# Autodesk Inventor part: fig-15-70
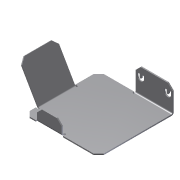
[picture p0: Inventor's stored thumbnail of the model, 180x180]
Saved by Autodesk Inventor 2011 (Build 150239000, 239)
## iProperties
Shininess: 77.0
Angle Display Precision: 2
Document Length Units: 11269
Document Angle Units: 11279
Document Time Units: 11290
Document Mass Units: 11283
Document Length Units Precision: 3
Document Angle Units Precision: 2
Created: 2002-04
Part Number: fig-15-70
Document SubType Name: Sheet Metal
Density: 1 g/cm^3
Sheet Metal Rule: Default
Density: 0.0
Volumn: 0.0
Area: 0.0
PropertySet Name: Model Information
Control State: 0
Master: False
Checked Out: False
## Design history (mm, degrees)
node "Face1"
  sketch "Sketch1"
    geometry: L1 (12.647, 25.882)-(12.647, -14.118); L2 (12.647, -14.118)-(-17.353, -14.118); L3 (-17.353, -14.118)-(-17.353, 15.882); L4 (-17.353, 15.882)-(-2.353, 15.882); L5 (-2.353, 15.882)-(-2.353, 25.882); L6 (-2.353, 25.882)-(12.647, 25.882); 1 further point
    constraints: 12 end point, 4 parallel, 1 perpendicular
    dimensions: "d5" = 30 distance of L2.end L3.end; "d6" = 10 distance of L4.end L5.end; "d7" = 15 distance of L3.end L4.end; "d25" = 15 distance of L5.end L1.start
sketch "Sketch3"
  geometry: L1 (10, -15)-(10, 0)
  constraints: 2 end point
feature "Fold3" sketch "Sketch3" dims "d26" = 0.5 (= BendRadius), "d27" = 90 deg, "d28" = 0.5 (= BendRadius), "d96" = 0.5 (= BendReliefWidth), "d97" = 0.25 (= BendReliefDepth), "d98" = 1 (= MinimumRemnant), "SeamGap" = 0.01, "Thickness" = 0.5
node "Flange2"
sketch "Sketch6"
  geometry: L1 (-6.914, 3.413)-(-5.843, 3.413); L2 (-5.843, 0.624)-(-6.914, 0.624); L3 (-6.914, 2.432)-(-5.843, 2.432); L4 (-5.843, 1.605)-(-6.914, 1.605); L5 (-6.914, 0.624)-(-6.914, 1.605); L6 (-6.914, 2.432)-(-6.914, 3.413); L7 (-6.914, 12.568)-(-6.914, 11.587); L8 (-6.914, 14.376)-(-6.914, 13.395); L9 (-6.914, 11.587)-(-5.843, 11.587); L10 (-5.843, 14.376)-(-6.914, 14.376); L11 (-6.914, 12.568)-(-5.843, 12.568); L12 (-5.843, 13.395)-(-6.914, 13.395); A1 r 1.394 centre (-5.843, 2.018) between (-5.843, 0.624) and (-5.843, 3.413); A2 r 0.413 centre (-5.843, 2.018) between (-5.843, 1.605) and (-5.843, 2.432); A3 r 1.394 centre (-5.843, 12.982) between (-5.843, 11.587) and (-5.843, 14.376); A4 r 0.413 centre (-5.843, 12.982) between (-5.843, 12.568) and (-5.843, 13.395)
  constraints: 24 end point, 8 point on circle, 4 centre point, 3 equal length, 1 perpendicular
cut "Cut1" sketch "Sketch6" dims "d49" = 0.5 (= Thickness), "d50" = 0
node "Flange3"
feature "Corner Chamfer3" dims "d107" = 2, "d108" = 6, angle "d109" = 45 deg
feature "Corner Chamfer4" dims "d110" = 2, "d111" = 6, angle "d112" = 45 deg
feature "Corner Chamfer5" dims "d113" = 2, "d114" = 6, angle "d115" = 45 deg
feature "Corner Chamfer6" dims "d116" = 2, "d117" = 6, angle "d118" = 45 deg
body "Solid1"
face "Plate1" dims "Thickness" = 0.5
sketch "Sketch5"
  geometry: L1 (20, 0)-(5, 0); L2 (5, 0)-(5, 15); L3 (5, 15)-(20, 15); L4 (20, 15)-(20, 0)
  constraints: 8 end point
face "Plate6" dims "d35" = 10, "d36" = 5, "d38" = 15, "d39" = 60 deg, "d40" = 0.5 (= BendRadius), "Thickness" = 0.5, "MinimumRemnant" = 1 (= 2 x Thickness), "BendReliefWidth" = 0.5 (= Thickness)
bend "Bend5" dims "d38" = 15, "d39" = 60 deg, "d40" = 0.5 (= BendRadius), "d99" = 0.5 (= BendReliefWidth), "d100" = 0.25 (= BendReliefDepth), "d101" = 1 (= MinimumRemnant), "SeamGap" = 0.01, "Thickness" = 0.5, "MinimumRemnant" = 1 (= 2 x Thickness), "BendReliefWidth" = 0.5 (= Thickness), "TransitionRadius" = 0.5 (= BendRadius)
sketch "Sketch7"
  geometry: L1 (25, 0)-(15, 0); L2 (15, 0)-(15, 5); L3 (15, 5)-(25, 5); L4 (25, 5)-(25, 0)
  constraints: 8 end point
face "Plate7" dims "d57" = 5, "d58" = 10, "d60" = 5, "d61" = 90 deg, "d62" = 0.5 (= BendRadius), "Thickness" = 0.5, "MinimumRemnant" = 1 (= 2 x Thickness), "BendReliefWidth" = 0.5 (= Thickness)
bend "Bend7" dims "d59" = 0.5 (= BendRadius), "d60" = 5, "d61" = 90 deg, "d62" = 0.5 (= BendRadius), "d102" = 0.5 (= BendReliefWidth), "d103" = 0.25 (= BendReliefDepth), "d104" = 1 (= MinimumRemnant), "SeamGap" = 0.01, "Thickness" = 0.5, "MinimumRemnant" = 1 (= 2 x Thickness), "BendReliefWidth" = 0.5 (= Thickness)
other parameters: "BendRadius" = 0.5 (= Thickness), "BendReliefDepth" = 0.25 (= 0.5 x Thickness), "CornerReliefSize" = 2 (= 4 x Thickness), "d0" = 0.5 (= BendRadius), "d13" = 0.5 (= BendRadius), "d31" = 0.5 (= BendRadius), "d37" = 0.5 (= BendRadius), "JacobiRadiusSize" = 0.5 (= Thickness), "GapSize" = 0.5 (= Thickness)
